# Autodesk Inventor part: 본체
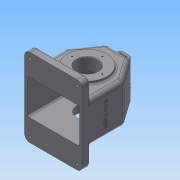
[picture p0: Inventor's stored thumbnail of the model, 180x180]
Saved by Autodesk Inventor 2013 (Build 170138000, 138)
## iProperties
Created: 2016-12
Part Number: 본체
Material: Generic
Document SubType Name: Modeling
Designer: Administrator
Density: 1 g/cm^3
Author: Administrator
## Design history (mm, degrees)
sketch "스케치1"
  geometry: L1 (-55, -65)-(-55, 15); L2 (-55, 15)-(-23.491, 60); L3 (-23.491, 60)-(23.491, 60); L4 (23.491, 60)-(55, 15); L5 (55, 15)-(55, -65); L6 (55, -65)-(-55, -65); 1 further point
  constraints: 12 end point, 3 parallel, 1 perpendicular, 1 vertical
  dimensions: "d0" = 110 distance of L5.end L1.start; "d2" = 80 distance of L4.end L5.end; "d3" = 125 distance between parallel lines of L6 L3; "d4" = 65 distance from line of L6 point (0, 0); "d5" = 55 distance from line of point (0, 0) L1; "d6" = 35 deg angle of L2 L1; "d7" = 35 deg angle of L4 L5
extrude "돌출1" new body sketch "스케치1" stored distance "d8" = 77; taper "d9" = 0 deg
fillet "모깎기1" dims "d10" = 10
fillet "모깎기2" dims "d11" = 8
feature "쉘1" dims "d12" = 5
sketch "스케치2"
  geometry: L1 (94, 0)-(0, 0) reference; L2 (102, 69)-(102, 8) reference; L3 (0, 77)-(94, 77) reference; L4 (-8, 8)-(-8, 69) reference; L5 (-8, 113.5)-(102, 113.5); L6 (102, 113.5)-(102, -36.5); L7 (102, -36.5)-(-8, -36.5); L8 (-8, -36.5)-(-8, 113.5); A1 r 8 centre (0, 8) between (-8, 8) and (0, 0) reference; A2 r 8 centre (94, 8) between (94, 0) and (102, 8) reference; A3 r 8 centre (94, 69) between (102, 69) and (94, 77) reference; A4 r 8 centre (0, 69) between (0, 77) and (-8, 69) reference; 1 further point
  constraints: 8 end point, 2 parallel, 1 horizontal, 1 perpendicular
  dimensions: "d15" = 150 distance of L5.end L6.end; "d17" = 110 distance of L5.start L5.end; "d18" = 55 distance from line of L8 point (47, 38.5); "d19" = 75 distance from line of L5 point (47, 38.5)
extrude "돌출2" join sketch "스케치2" distance "d20" = 15; taper "d21" = 0 deg
fillet "모깎기3" dims "d22" = 10
sketch "스케치3"
  geometry: C1 r 37.5 at (0, 0); 1 further point
  constraints: 1 centre point, 1 coincident
  dimensions: "d23" = 75 diameter of C1
extrude "돌출3" join sketch "스케치3" distance "d24" = 5; taper "d25" = 0 deg
sketch "스케치4"
  geometry: C1 r 31 at (0, 0); 1 further point
  constraints: 1 centre point, 1 coincident
  dimensions: "d26" = 62 diameter of C1
extrude "돌출4" join sketch "스케치4" distance "d27" = 10; taper "d28" = 0 deg
node "작업 평면1"
sketch "스케치5"
  geometry: C1 r 27 at (0, 0); 1 further point
  constraints: 1 centre point, 1 coincident
  dimensions: "d30" = 54 diameter of C1
extrude "돌출5" join sketch "스케치5" stored distance "d31" = 10; taper "d32" = 45 deg
sketch "스케치6"
  geometry: C1 r 37.5 at (0, 0) reference; C2 r 20 at (0, 0)
  constraints: 1 centre point, 1 coincident
  dimensions: "d33" = 40 diameter of C2
extrude "돌출6" cut sketch "스케치6" stored distance "d34" = 10; taper "d35" = 0 deg
chamfer "모따기1" distance "d36" = 1; stored, may be unused: second distance "d37" = 2, angle "d38" = 45 deg
fillet "모깎기4" dims "d39" = 3
fillet "모깎기5" dims "d40" = 3
fillet "모깎기6" dims "d41" = 3
sketch "스케치7"
  geometry: L1 (99, 26.5)-(99, 1.798) reference; L2 (2, 33.5)-(92, 33.5) reference; L3 (-5, 1.798)-(-5, 26.5) reference; L4 (94, 3)-(0, 3) reference; A1 r 7 centre (2, -103.5) between (-5, -103.5) and (2, -110.5) reference; A2 r 7 centre (92, -103.5) between (92, -110.5) and (99, -103.5) reference; A3 r 11 centre (94, -8) between (99, 1.798) and (94, 3) reference; A4 r 7 centre (92, 26.5) between (99, 26.5) and (92, 33.5) reference; A5 r 7 centre (2, 26.5) between (2, 33.5) and (-5, 26.5) reference; A6 r 11 centre (0, -8) between (0, 3) and (-5, 1.798) reference; 5 further points
  constraints: 4 coincident
hole "구멍1" sketch "스케치7" at (2, -103.5), (92, -103.5), (2, 26.5), (92, 26.5) diameter "d42" = 5; stored, may be unused: countersink angle "d46" = 90 deg, drill point angle "d48" = 118 deg; dims "d43" = 6, "d44" = 12, "d45" = 5, "d47" = 8
node "작업 평면2"
sketch "스케치8"
  geometry: L1 (-12.5, 59.994)-(-12.5, 67); L2 (-4.5, 75)-(4.5, 75); L3 (12.5, 67)-(12.5, 59.994); L4 (55, 11.847)-(55, -65) reference; L5 (55, -65)-(50, -65) reference; L6 (50, -65)-(50, 11.847) reference; L7 (49.096, 14.715)-(22.381, 52.868) reference; L8 (18.285, 55)-(-18.285, 55) reference; L9 (-22.381, 52.868)-(-49.096, 14.715) reference; L10 (-50, 11.847)-(-50, -65) reference; L11 (-50, -65)-(-55, -65) reference; L12 (-55, -65)-(-55, 11.847) reference; L13 (-53.192, 17.583)-(-26.477, 55.736) reference; L14 (-18.285, 60)-(18.285, 60) reference; L15 (26.477, 55.736)-(53.192, 17.583) reference; L16 (47, -65)-(-47, -65) reference; A1 r 5 centre (45, 11.847) between (50, 11.847) and (49.096, 14.715) reference; A2 r 5 centre (18.285, 50) between (22.381, 52.868) and (18.285, 55) reference; A3 r 5 centre (-18.285, 50) between (-18.285, 55) and (-22.381, 52.868) reference; A4 r 5 centre (-45, 11.847) between (-49.096, 14.715) and (-50, 11.847) reference; A5 r 10 centre (-45, 11.847) between (-53.192, 17.583) and (-55, 11.847) reference; A6 r 10 centre (-18.285, 50) between (-18.285, 60) and (-26.477, 55.736) reference; A7 r 10 centre (18.285, 50) between (26.477, 55.736) and (18.285, 60) reference; A8 r 10 centre (45, 11.847) between (55, 11.847) and (53.192, 17.583) reference; A9 r 8 centre (4.5, 67) between (12.5, 67) and (4.5, 75); A10 r 8 centre (-4.5, 67) between (-4.5, 75) and (-12.5, 67); 3 further points
  constraints: 6 end point, 4 point on circle, 4 point on line, 4 tangent, 2 centre point, 1 equal radius, 1 parallel, 1 perpendicular, 1 vertical
  dimensions: "d50" = 140 distance between parallel lines of L16 L2; "d51" = 25 distance of point (-12.5, 75) point (12.5, 75); "d52" = 12.5 distance from line of point (0, 0) L1; "d59" = 8 radius of A9
feature "리브1" sketch "스케치8" dims "d53" = 5, "d54" = 8, "d55" = 0, "d56" = 0, "d57" = 1, "d58" = 1
fillet "모깎기7" dims "d60" = 1
fillet "모깎기9" dims "d62" = 1
fillet "모깎기10" dims "d63" = 1
sketch "스케치9"
  geometry: C1 r 31 at (0, 0) reference; 1 further point
  constraints: 1 vertical alignment
  dimensions: "d64" = 26 distance of C1.centre point (0, 26)
hole "구멍2" sketch "스케치9" at (0, 26) diameter "d65" = 2.459; stored, may be unused: countersink angle "d69" = 90 deg, drill point angle "d71" = 118 deg; dims "d66" = 6, "d67" = 12, "d68" = 5, "d70" = 8
sketch "스케치10"
  geometry: C1 r 37.5 at (0, 0) reference; 1 further point
  constraints: 1 vertical alignment
  dimensions: "d75" = 29 distance of C1.centre point (0, 29)
hole "구멍3" sketch "스케치10" at (0, 29) diameter "d76" = 2.459; stored, may be unused: countersink angle "d80" = 90 deg, drill point angle "d82" = 118 deg; dims "d77" = 6, "d78" = 12, "d79" = 5, "d81" = 8
sketch "스케치11"
  geometry: L1 (-34.5, -76.847)-(95.5, -76.847) reference; L2 (-8, 0)-(-8, -58.847) reference; 2 further points
  constraints: 1 other
  dimensions: "d86" = 38.5 distance from line of L2 point (30.5, -31.847); "d87" = 45 distance from line of L1 point (30.5, -31.847)
feature "엠보싱1" sketch "스케치11" dims "d88" = 0.5, "d89" = 0
node "솔리드1"
mirror "대칭2"
pattern_circular "원형 패턴1" dims angle "d73" = 360 deg
pattern_circular "원형 패턴2" dims angle "d84" = 360 deg
node "투영된 루프1"
node "절단 모서리 투영1"
other parameters: "d29" = -24, "d49" = 18
